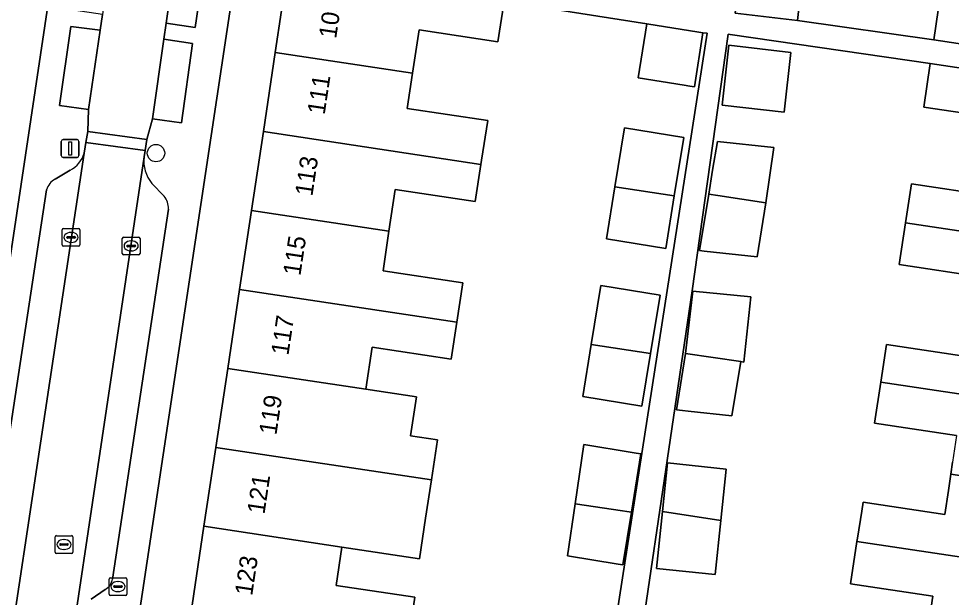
# Model space of a CAD drawing. Extents: x 163008 to 163854, y 382777 to 383982.
# Drawn here: x 163614.8 to 163667.4, y 383271.6 to 383304.2 of the extents above; entities that cross this region are included whole.
import ezdxf

# ---------------------------------------------------------------- set-up
doc = ezdxf.new("R2010")
doc.units = 0
for name, color, linetype in [('IMGEO_Boom', 7, 'Continuous'), ('IMGEO_Brandkraan', 7, 'Continuous'), ('IMGEO_Erf', 7, 'Continuous'), ('IMGEO_Kolk', 7, 'Continuous'), ('IMGEO_Lichtmast', 7, 'Continuous'), ('IMGEO_Pand', 7, 'Continuous'), ('IMGEO_Pand_nummerreeks', 7, 'Continuous'), ('IMGEO_Parkeervlak_open', 7, 'Continuous'), ('IMGEO_Rijbaan_lokaal_open', 7, 'Continuous'), ('IMGEO_Rioolput', 7, 'Continuous'), ('IMGEO_Voetpad_open', 7, 'Continuous')]:
    doc.layers.add(name, color=color, linetype=linetype)

msp = doc.modelspace()

# ---------------------------------------------------------------- linework, layer by layer
at = {"layer": 'IMGEO_Boom'}
msp.add_circle((163622.543, 383296.649), 0.489, dxfattribs=at)
at = {"layer": 'IMGEO_Brandkraan'}
for p, q in [((163619.898, 383271.768), (163619.898, 383272.62)), ((163619.973, 383272.694), (163620.825, 383272.694)), ((163620.386, 383272.474), (163620.411, 383272.474)), ((163620.899, 383272.62), (163620.899, 383271.768)), ((163620.157, 383272.188), (163620.157, 383272.2)), ((163620.595, 383272.151), (163620.197, 383272.151)), ((163620.2, 383272.237), (163620.598, 383272.237)), ((163620.409, 383271.914), (163620.384, 383271.914)), ((163620.641, 383272.2), (163620.641, 383272.188)), ((163620.825, 383271.694), (163619.973, 383271.694))]:
    msp.add_line(p, q, dxfattribs=at)
for points in [[(163619.898, 383271.768), (163619.898, 383272.62)], [(163619.973, 383272.694), (163620.825, 383272.694)], [(163620.899, 383272.62), (163620.899, 383271.768)], [(163620.825, 383271.694), (163619.973, 383271.694)]]:
    msp.add_lwpolyline(points, dxfattribs=at)
for centre, radius, start, end in [((163619.975, 383272.618), 0.0765, 91.552, 178.448), ((163619.975, 383272.618), 0.0765, 91.552, 178.448), ((163620.823, 383272.618), 0.0765, 1.552, 88.448), ((163620.823, 383272.618), 0.0765, 1.552, 88.448), ((163620.197, 383272.197), 0.0403, 85.8775, 175.7526), ((163620.194, 383272.187), 0.0366, 178.938, 274.7102), ((163620.598, 383272.194), 0.043, 264.8664, 352.4533), ((163620.602, 383272.199), 0.0386, 1.7309, 96.639), ((163619.975, 383271.77), 0.0765, 181.552, 268.448), ((163619.975, 383271.77), 0.0765, 181.552, 268.448), ((163620.823, 383271.77), 0.0765, 271.552, 358.448), ((163620.823, 383271.77), 0.0765, 271.552, 358.448)]:
    msp.add_arc(centre, radius, start, end, dxfattribs=at)
for centre, major_axis, ratio, start_param, end_param in [((163620.385, 383272.194), (-0.387, 0.002), 0.722429, 4.712389, 7.853982), ((163620.41, 383272.194), (-0.39, 0.002), 0.717154, 1.570796, 4.712389)]:
    msp.add_ellipse(centre, major_axis=major_axis, ratio=ratio, start_param=start_param, end_param=end_param, dxfattribs=at)
at = {"layer": 'IMGEO_Erf'}
for points in [[(163679.889, 383360.907), (163664.081, 383363.249), (163659.743, 383335.218), (163658.351, 383326.217), (163656.981, 383317.216), (163656.609, 383313.683), (163656.621, 383313.742), (163657.071, 383316.66), (163660.231, 383316.328), (163659.748, 383313.212), (163659.274, 383310.16), (163656.61, 383310.44), (163656.272, 383310.476), (163655.965, 383307.874), (163659.102, 383307.514), (163658.715, 383304.141), (163666.408, 383303.048), (163666.795, 383305.63), (163667.104, 383307.692), (163671.602, 383307.017)], [(163648.55, 383270.749), (163653.627, 383303.427), (163653.376, 383303.437), (163652.903, 383300.384), (163652.653, 383300.425), (163652.333, 383300.477), (163649.743, 383300.899), (163650.217, 383303.952), (163642.171, 383305.204), (163641.83, 383302.939), (163637.385, 383303.608), (163637.015, 383301.155), (163636.715, 383299.165), (163641.249, 383298.483), (163640.892, 383296.249), (163640.857, 383296.013), (163640.542, 383293.921), (163636.036, 383294.6), (163635.681, 383292.24), (163635.346, 383290.016), (163639.841, 383289.339), (163639.505, 383287.107), (163639.191, 383285.023), (163634.731, 383285.695), (163634.374, 383283.327), (163637.226, 383282.896), (163636.896, 383280.699), (163638.415, 383280.47), (163638.075, 383278.213), (163637.749, 383276.051), (163637.404, 383273.759), (163633.028, 383274.42), (163632.704, 383272.264), (163637.142, 383271.595), (163636.796, 383269.296)], [(163670.3, 383298.582), (163665.839, 383299.251), (163666.207, 383301.704), (163654.924, 383303.349), (163654.815, 383303.364), (163652.783, 383288.887), (163651.472, 383279.957), (163649.867, 383269.108), (163648.518, 383260.134), (163647.168, 383251.16), (163646.796, 383247.628), (163646.572, 383246.132), (163646.459, 383244.42)], [(163669.049, 383289.67), (163666.07, 383290.117), (163664.464, 383290.358), (163664.817, 383292.711), (163665.147, 383294.915), (163669.648, 383294.24)], [(163667.691, 383280.723), (163663.069, 383281.416), (163663.417, 383283.732), (163663.735, 383285.854), (163668.374, 383285.159)], [(163666.041, 383269.554), (163666.356, 383271.65), (163661.713, 383272.346), (163662.073, 383274.743), (163662.101, 383274.932), (163662.355, 383276.442), (163662.431, 383276.95), (163667.028, 383276.261), (163667.231, 383277.615), (163667.364, 383278.545), (163667.464, 383279.211)]]:
    msp.add_lwpolyline(points, dxfattribs=at)
for points in [[(163617.064, 383309.129), (163614.133, 383309.568), (163613.435, 383304.901), (163612.765, 383300.418), (163612.095, 383295.936), (163611.424, 383291.454), (163610.754, 383286.972), (163610.084, 383282.49), (163609.414, 383278.008), (163608.744, 383273.526), (163608.073, 383269.044), (163607.403, 383264.561), (163606.733, 383260.079), (163606.062, 383255.594), (163605.388, 383251.086), (163608.303, 383250.604)], [(163625.915, 383280.05), (163626.586, 383284.503), (163627.256, 383288.957), (163627.927, 383293.411), (163628.598, 383297.865), (163629.269, 383302.324), (163629.986, 383307.085), (163627.135, 383307.514), (163618.487, 383250), (163618.346, 383249.06), (163620.803, 383248.742), (163620.284, 383245.414), (163620.668, 383245.357), (163621.015, 383247.666), (163621.194, 383248.7), (163621.39, 383250), (163621.892, 383253.327), (163622.562, 383257.78), (163623.232, 383262.235), (163623.903, 383266.688), (163624.574, 383271.142), (163625.244, 383275.595)], [(163654.467, 383299.363), (163654.564, 383300.206), (163654.854, 383302.736), (163658.354, 383302.334), (163657.967, 383298.961)], [(163647.949, 383291.823), (163648.428, 383294.752), (163648.972, 383298.083), (163652.311, 383297.537), (163651.773, 383294.246), (163651.287, 383291.277)], [(163653.715, 383294.339), (163653.935, 383295.683), (163654.202, 383297.309), (163657.393, 383296.973), (163656.94, 383293.855), (163656.44, 383290.806), (163653.455, 383291.12), (163653.193, 383291.148)], [(163647.086, 383285.845), (163647.63, 383289.175), (163650.969, 383288.629), (163650.431, 383285.339), (163649.945, 383282.369), (163646.607, 383282.915)], [(163655.703, 383284.86), (163655.52, 383284.887), (163655.021, 383281.837), (163652.554, 383282.097), (163652.24, 383282.13), (163651.889, 383282.166), (163652.411, 383285.354), (163652.818, 383288.858), (163656.09, 383288.539)], [(163646.676, 383280.205), (163649.406, 383279.758), (163649.628, 383279.722), (163649.892, 383279.679), (163649.354, 383276.391), (163648.869, 383273.419), (163648.604, 383273.462), (163645.752, 383273.929), (163646.185, 383276.87)], [(163654.392, 383275.93), (163654.07, 383272.87), (163650.763, 383273.218), (163651.1, 383276.425), (163651.389, 383279.174), (163654.697, 383278.826)]]:
    msp.add_lwpolyline(points, close=True, dxfattribs=at)
at = {"layer": 'IMGEO_Kolk'}
for p, q in [((163617.329, 383292.397), (163618.181, 383292.397)), ((163617.254, 383291.471), (163617.254, 383292.323)), ((163617.513, 383291.891), (163617.513, 383291.903)), ((163617.951, 383291.854), (163617.553, 383291.854)), ((163617.556, 383291.94), (163617.954, 383291.94)), ((163617.742, 383292.177), (163617.767, 383292.177)), ((163617.997, 383291.903), (163617.997, 383291.891)), ((163618.255, 383292.323), (163618.255, 383291.471)), ((163620.641, 383290.988), (163620.641, 383291.84)), ((163620.716, 383291.914), (163621.568, 383291.914)), ((163621.642, 383291.84), (163621.642, 383290.988)), ((163618.181, 383291.397), (163617.329, 383291.397)), ((163617.765, 383291.617), (163617.74, 383291.617)), ((163620.9, 383291.408), (163620.9, 383291.42)), ((163621.338, 383291.371), (163620.94, 383291.371)), ((163620.943, 383291.457), (163621.341, 383291.457)), ((163621.129, 383291.694), (163621.154, 383291.694)), ((163621.384, 383291.42), (163621.384, 383291.408)), ((163621.568, 383290.914), (163620.716, 383290.914)), ((163621.152, 383291.134), (163621.127, 383291.134))]:
    msp.add_line(p, q, dxfattribs=at)
for points in [[(163617.329, 383292.397), (163618.181, 383292.397)], [(163617.254, 383291.471), (163617.254, 383292.323)], [(163618.255, 383292.323), (163618.255, 383291.471)], [(163620.641, 383290.988), (163620.641, 383291.84)], [(163620.716, 383291.914), (163621.568, 383291.914)], [(163621.642, 383291.84), (163621.642, 383290.988)], [(163618.181, 383291.397), (163617.329, 383291.397)], [(163621.568, 383290.914), (163620.716, 383290.914)]]:
    msp.add_lwpolyline(points, dxfattribs=at)
for centre, radius, start, end in [((163617.331, 383292.321), 0.0765, 91.552, 178.448), ((163617.331, 383292.321), 0.0765, 91.552, 178.448), ((163618.179, 383292.321), 0.0765, 1.552, 88.448), ((163618.179, 383292.321), 0.0765, 1.552, 88.448), ((163617.553, 383291.9), 0.0403, 85.8775, 175.7526), ((163617.55, 383291.89), 0.0366, 178.938, 274.7102), ((163617.954, 383291.897), 0.043, 264.8664, 352.4533), ((163617.958, 383291.902), 0.0386, 1.7309, 96.639), ((163620.718, 383291.838), 0.0765, 91.552, 178.448), ((163620.718, 383291.838), 0.0765, 91.552, 178.448), ((163621.566, 383291.838), 0.0765, 1.552, 88.448), ((163621.566, 383291.838), 0.0765, 1.552, 88.448), ((163617.331, 383291.473), 0.0765, 181.552, 268.448), ((163617.331, 383291.473), 0.0765, 181.552, 268.448), ((163618.179, 383291.473), 0.0765, 271.552, 358.448), ((163618.179, 383291.473), 0.0765, 271.552, 358.448), ((163620.94, 383291.417), 0.0403, 85.8775, 175.7526), ((163620.937, 383291.407), 0.0366, 178.938, 274.7102), ((163621.341, 383291.414), 0.043, 264.8664, 352.4533), ((163621.345, 383291.419), 0.0386, 1.7309, 96.639), ((163620.718, 383290.99), 0.0765, 181.552, 268.448), ((163620.718, 383290.99), 0.0765, 181.552, 268.448), ((163621.566, 383290.99), 0.0765, 271.552, 358.448), ((163621.566, 383290.99), 0.0765, 271.552, 358.448)]:
    msp.add_arc(centre, radius, start, end, dxfattribs=at)
for centre, major_axis, ratio, start_param, end_param in [((163617.741, 383291.897), (-0.387, 0.002), 0.722429, 4.712389, 7.853982), ((163617.766, 383291.897), (-0.39, 0.002), 0.717154, 1.570796, 4.712389), ((163621.128, 383291.414), (-0.387, 0.002), 0.722429, 4.712389, 7.853982), ((163621.153, 383291.414), (-0.39, 0.002), 0.717154, 1.570796, 4.712389)]:
    msp.add_ellipse(centre, major_axis=major_axis, ratio=ratio, start_param=start_param, end_param=end_param, dxfattribs=at)
at = {"layer": 'IMGEO_Lichtmast'}
for p, q in [((163617.204, 383296.513), (163617.204, 383297.313)), ((163617.204, 383297.313), (163617.204, 383296.513)), ((163617.304, 383297.413), (163618.094, 383297.413)), ((163618.094, 383297.413), (163617.304, 383297.413)), ((163618.194, 383297.313), (163618.194, 383296.513)), ((163618.194, 383296.513), (163618.194, 383297.313)), ((163618.094, 383296.413), (163617.304, 383296.413)), ((163617.304, 383296.413), (163618.094, 383296.413))]:
    msp.add_line(p, q, dxfattribs=at)
msp.add_lwpolyline([(163617.624, 383297.288), (163617.774, 383297.288), (163617.774, 383296.538), (163617.624, 383296.538), (163617.624, 383297.288)], dxfattribs=at)
for centre, start, end in [((163617.304, 383297.313), 90, 180), ((163617.304, 383297.313), 90, 180), ((163618.094, 383297.313), 0, 90), ((163618.094, 383297.313), 360, 90), ((163617.304, 383296.513), 180, 270), ((163617.304, 383296.513), 180, 270), ((163618.094, 383296.513), 270, 0), ((163618.094, 383296.513), 270, 0)]:
    msp.add_arc(centre, 0.1, start, end, dxfattribs=at)
at = {"layer": 'IMGEO_Pand'}
for points in [[(163659.102, 383307.514), (163655.965, 383307.874), (163655.602, 383307.916), (163655.215, 383304.543), (163658.715, 383304.141)], [(163679.333, 383305.856), (163671.602, 383307.017), (163667.104, 383307.692), (163666.795, 383305.63), (163666.408, 383303.048), (163670.912, 383302.373), (163673.691, 383301.96), (163678.637, 383301.225)], [(163629.269, 383302.324), (163637.015, 383301.155), (163637.385, 383303.608), (163641.83, 383302.939), (163642.171, 383305.204), (163637.727, 383305.873), (163634.926, 383306.312), (163629.986, 383307.085)], [(163653.376, 383303.437), (163653.15, 383303.474), (163650.217, 383303.952), (163649.743, 383300.899), (163652.333, 383300.477), (163652.653, 383300.425), (163652.903, 383300.384)], [(163654.564, 383300.206), (163654.467, 383299.363), (163657.967, 383298.961), (163658.354, 383302.334), (163654.854, 383302.736)], [(163636.715, 383299.165), (163637.015, 383301.155), (163629.269, 383302.324), (163628.598, 383297.865), (163640.857, 383296.013), (163640.892, 383296.249), (163641.249, 383298.483)], [(163678.43, 383299.85), (163673.488, 383300.605), (163670.71, 383301.029), (163666.207, 383301.704), (163665.839, 383299.251), (163670.3, 383298.582), (163669.992, 383296.531), (163677.757, 383295.368)], [(163640.857, 383296.013), (163628.598, 383297.865), (163627.927, 383293.411), (163635.681, 383292.24), (163636.036, 383294.6), (163640.542, 383293.921)], [(163651.773, 383294.246), (163652.311, 383297.537), (163648.972, 383298.083), (163648.428, 383294.752)], [(163653.715, 383294.339), (163654.235, 383294.261), (163656.94, 383293.855), (163657.393, 383296.973), (163654.202, 383297.309), (163653.935, 383295.683)], [(163669.992, 383296.531), (163669.648, 383294.24), (163665.147, 383294.915), (163664.817, 383292.711), (163677.082, 383290.874), (163677.757, 383295.368)], [(163651.773, 383294.246), (163648.428, 383294.752), (163647.949, 383291.823), (163651.287, 383291.277)], [(163656.94, 383293.855), (163654.235, 383294.261), (163653.715, 383294.339), (163653.193, 383291.148), (163653.455, 383291.12), (163656.44, 383290.806)], [(163635.681, 383292.24), (163627.927, 383293.411), (163627.256, 383288.957), (163639.505, 383287.107), (163639.841, 383289.339), (163635.346, 383290.016)], [(163677.082, 383290.874), (163664.817, 383292.711), (163664.464, 383290.358), (163666.07, 383290.117), (163669.049, 383289.67), (163668.823, 383287.517), (163676.407, 383286.381)], [(163627.256, 383288.957), (163626.586, 383284.503), (163634.374, 383283.327), (163634.731, 383285.695), (163639.191, 383285.023), (163639.505, 383287.107)], [(163647.086, 383285.845), (163650.431, 383285.339), (163650.969, 383288.629), (163647.63, 383289.175)], [(163656.09, 383288.539), (163652.818, 383288.858), (163652.411, 383285.354), (163655.52, 383284.887), (163655.703, 383284.86)], [(163676.407, 383286.381), (163668.823, 383287.517), (163668.708, 383287.389), (163668.374, 383285.159), (163663.735, 383285.854), (163663.417, 383283.732), (163675.732, 383281.887)], [(163647.086, 383285.845), (163646.607, 383282.915), (163649.945, 383282.369), (163650.431, 383285.339)], [(163655.52, 383284.887), (163652.411, 383285.354), (163651.889, 383282.166), (163652.24, 383282.13), (163652.554, 383282.097), (163655.021, 383281.837)], [(163634.374, 383283.327), (163626.586, 383284.503), (163625.915, 383280.05), (163638.075, 383278.213), (163638.415, 383280.47), (163636.896, 383280.699), (163637.226, 383282.896)], [(163675.732, 383281.887), (163663.417, 383283.732), (163663.069, 383281.416), (163667.691, 383280.723), (163667.464, 383279.211), (163667.364, 383278.545), (163675.057, 383277.393)], [(163633.028, 383274.42), (163637.404, 383273.759), (163637.749, 383276.051), (163638.075, 383278.213), (163625.915, 383280.05), (163625.244, 383275.595)], [(163646.185, 383276.87), (163648.853, 383276.467), (163649.09, 383276.431), (163649.354, 383276.391), (163649.892, 383279.679), (163649.628, 383279.722), (163649.406, 383279.758), (163646.676, 383280.205)], [(163651.1, 383276.425), (163654.392, 383275.93), (163654.697, 383278.826), (163651.389, 383279.174)], [(163675.057, 383277.393), (163667.364, 383278.545), (163667.231, 383277.615), (163667.028, 383276.261), (163662.431, 383276.95), (163662.355, 383276.442), (163662.101, 383274.932), (163662.073, 383274.743), (163674.382, 383272.9)], [(163649.354, 383276.391), (163649.09, 383276.431), (163648.853, 383276.467), (163646.185, 383276.87), (163645.752, 383273.929), (163648.604, 383273.462), (163648.869, 383273.419)], [(163651.1, 383276.425), (163650.763, 383273.218), (163654.07, 383272.87), (163654.392, 383275.93)], [(163633.028, 383274.42), (163625.244, 383275.595), (163624.574, 383271.142), (163636.796, 383269.296), (163637.142, 383271.595), (163632.704, 383272.264)], [(163674.382, 383272.9), (163662.073, 383274.743), (163661.713, 383272.346), (163666.356, 383271.65), (163666.041, 383269.554), (163673.707, 383268.406)]]:
    msp.add_lwpolyline(points, close=True, dxfattribs=at)
at = {"layer": 'IMGEO_Parkeervlak_open'}
for points in [[(163624.755, 383303.737), (163625.406, 383308.216), (163623.763, 383308.45), (163623.109, 383303.985)], [(163618.727, 383299.103), (163619.395, 383303.584), (163617.74, 383303.798), (163617.102, 383299.329)], [(163622.984, 383303.076), (163622.34, 383298.594), (163623.974, 383298.368), (163624.606, 383302.837)]]:
    msp.add_lwpolyline(points, close=True, dxfattribs=at)
for points in [[(163611.614, 383251.055), (163618.49, 383296.655)], [(163621.871, 383296.439), (163615.006, 383250.516)], [(163617.699, 383295.693), (163616.854, 383295.186)], [(163616.373, 383294.574), (163613.188, 383273.75)], [(163623.004, 383294.222), (163622.314, 383294.944)], [(163620.094, 383272.62), (163623.243, 383293.494)], [(163618.88, 383271.48), (163619.683, 383272.03)]]:
    msp.add_lwpolyline(points, dxfattribs=at)
for centre, radius, start, end in [((163617.028, 383297.051), 1.515, 296.2957, 344.8471), ((163623.813, 383296.201), 1.957, 173.0259, 219.9854), ((163617.332, 383294.315), 0.993, 118.7682, 164.9008), ((163622.142, 383293.536), 1.101, 357.8185, 38.5312), ((163619.234, 383272.781), 0.875, 300.8838, 349.3933)]:
    msp.add_arc(centre, radius, start, end, dxfattribs=at)
at = {"layer": 'IMGEO_Rijbaan_lokaal_open'}
for points in [[(163623.763, 383308.45), (163623.98, 383309.644), (163624.616, 383314.127), (163624.75, 383315.017), (163625.462, 383319.502), (163625.602, 383320.993), (163622.153, 383321.469), (163621.806, 383320.011), (163621.152, 383315.54), (163620.987, 383314.543), (163620.326, 383310.068), (163620.158, 383308.956), (163619.533, 383304.478), (163619.395, 383303.584), (163618.727, 383299.103), (163618.697, 383297.877), (163622.019, 383297.425), (163622.34, 383298.594), (163622.984, 383303.076), (163623.109, 383303.985)], [(163621.924, 383296.792), (163622.019, 383297.425), (163618.697, 383297.877), (163618.586, 383297.246)], [(163614.953, 383250.174), (163615.006, 383250.516), (163621.871, 383296.439), (163621.924, 383296.792), (163618.586, 383297.246), (163618.543, 383297.004), (163618.49, 383296.655), (163611.614, 383251.055), (163611.551, 383250.689)]]:
    msp.add_lwpolyline(points, close=True, dxfattribs=at)
at = {"layer": 'IMGEO_Rioolput'}
for p, q in [((163616.927, 383275.067), (163617.779, 383275.067)), ((163616.852, 383274.141), (163616.852, 383274.993)), ((163617.111, 383274.561), (163617.111, 383274.573)), ((163617.549, 383274.524), (163617.151, 383274.524)), ((163617.154, 383274.61), (163617.552, 383274.61)), ((163617.34, 383274.847), (163617.365, 383274.847)), ((163617.595, 383274.573), (163617.595, 383274.561)), ((163617.853, 383274.993), (163617.853, 383274.141)), ((163617.779, 383274.067), (163616.927, 383274.067)), ((163617.363, 383274.287), (163617.338, 383274.287))]:
    msp.add_line(p, q, dxfattribs=at)
for points in [[(163616.927, 383275.067), (163617.779, 383275.067)], [(163616.852, 383274.141), (163616.852, 383274.993)], [(163617.853, 383274.993), (163617.853, 383274.141)], [(163617.779, 383274.067), (163616.927, 383274.067)]]:
    msp.add_lwpolyline(points, dxfattribs=at)
for centre, radius, start, end in [((163616.929, 383274.991), 0.0765, 91.552, 178.448), ((163616.929, 383274.991), 0.0765, 91.552, 178.448), ((163617.777, 383274.991), 0.0765, 1.552, 88.448), ((163617.777, 383274.991), 0.0765, 1.552, 88.448), ((163617.151, 383274.57), 0.0403, 85.8775, 175.7526), ((163617.148, 383274.56), 0.0366, 178.938, 274.7102), ((163617.552, 383274.567), 0.043, 264.8664, 352.4533), ((163617.556, 383274.572), 0.0386, 1.7309, 96.639), ((163616.929, 383274.143), 0.0765, 181.552, 268.448), ((163616.929, 383274.143), 0.0765, 181.552, 268.448), ((163617.777, 383274.143), 0.0765, 271.552, 358.448), ((163617.777, 383274.143), 0.0765, 271.552, 358.448)]:
    msp.add_arc(centre, radius, start, end, dxfattribs=at)
for centre, major_axis, ratio, start_param, end_param in [((163617.339, 383274.567), (-0.387, 0.002), 0.722429, 4.712389, 7.853982), ((163617.364, 383274.567), (-0.39, 0.002), 0.717154, 1.570796, 4.712389)]:
    msp.add_ellipse(centre, major_axis=major_axis, ratio=ratio, start_param=start_param, end_param=end_param, dxfattribs=at)
at = {"layer": 'IMGEO_Voetpad_open'}
for points in [[(163629.103, 383367.415), (163629.166, 383367.856), (163629.256, 383368.49), (163626.017, 383368.942), (163617.252, 383310.387), (163617.064, 383309.129), (163608.303, 383250.604), (163611.443, 383250.058), (163611.551, 383250.689), (163611.614, 383251.055)], [(163670.912, 383302.373), (163666.408, 383303.048), (163658.715, 383304.141), (163655.215, 383304.543), (163655.602, 383307.916), (163655.965, 383307.874), (163656.272, 383310.476), (163656.089, 383310.495), (163656.609, 383313.683), (163656.981, 383317.216), (163658.351, 383326.217), (163659.743, 383335.218), (163664.081, 383363.249), (163679.889, 383360.907)], [(163618.697, 383297.877), (163618.727, 383299.103), (163617.102, 383299.329), (163617.74, 383303.798), (163619.395, 383303.584), (163619.533, 383304.478), (163617.885, 383304.72), (163618.543, 383309.192), (163620.158, 383308.956), (163620.326, 383310.068), (163618.712, 383310.303), (163619.348, 383314.786), (163620.987, 383314.543), (163621.152, 383315.54), (163619.498, 383315.767), (163620.186, 383320.23), (163621.806, 383320.011), (163622.153, 383321.469), (163622.266, 383322.099), (163622.309, 383322.342)], [(163625.711, 383321.848), (163625.683, 383321.628), (163625.602, 383320.993), (163625.462, 383319.502), (163627.046, 383319.27), (163626.406, 383314.773), (163624.75, 383315.017), (163624.616, 383314.127), (163626.255, 383313.884), (163625.594, 383309.409), (163623.98, 383309.644), (163623.763, 383308.45), (163625.406, 383308.216), (163624.755, 383303.737), (163623.109, 383303.985), (163622.984, 383303.076), (163624.606, 383302.837), (163623.974, 383298.368), (163622.34, 383298.594), (163622.019, 383297.425), (163621.924, 383296.792), (163621.871, 383296.439)], [(163615.006, 383250.516), (163614.953, 383250.174), (163614.926, 383250), (163614.854, 383249.541), (163618.346, 383249.06), (163618.487, 383250), (163627.135, 383307.514)], [(163642.171, 383305.204), (163650.217, 383303.952), (163653.15, 383303.474), (163653.376, 383303.437), (163653.627, 383303.427), (163648.55, 383270.749), (163648.04, 383267.457), (163647.531, 383264.172), (163647.244, 383262.318), (163646.661, 383258.555), (163646.198, 383255.416), (163646.002, 383254.084), (163645.787, 383252.624), (163645.347, 383249.643), (163644.859, 383246.335), (163644.672, 383245.046), (163628.784, 383247.565), (163626.139, 383247.957), (163621.194, 383248.7), (163621.015, 383247.666), (163625.99, 383246.918), (163629.577, 383246.379), (163629.397, 383245.183)], [(163669.638, 383241.316), (163664.694, 383242.058), (163662.245, 383242.425), (163649.766, 383244.072), (163646.459, 383244.42), (163646.572, 383246.132), (163646.796, 383247.628), (163647.168, 383251.16), (163648.518, 383260.134), (163649.867, 383269.108), (163651.472, 383279.957), (163652.783, 383288.887), (163654.815, 383303.364), (163654.924, 383303.349), (163666.207, 383301.704), (163670.71, 383301.029)], [(163618.49, 383296.655), (163618.543, 383297.004), (163618.586, 383297.246), (163618.697, 383297.877)], [(163616.854, 383295.186), (163617.699, 383295.693)], [(163613.188, 383273.75), (163616.373, 383294.574)], [(163622.314, 383294.944), (163623.004, 383294.222)], [(163623.243, 383293.494), (163620.094, 383272.62)], [(163619.683, 383272.03), (163618.88, 383271.48)]]:
    msp.add_lwpolyline(points, dxfattribs=at)
for centre, radius, start, end in [((163617.028, 383297.051), 1.515, 296.2957, 344.8471), ((163623.813, 383296.201), 1.957, 173.0259, 219.9854), ((163617.332, 383294.315), 0.993, 118.7682, 164.9008), ((163622.142, 383293.536), 1.101, 357.8185, 38.5312), ((163619.234, 383272.781), 0.875, 300.8838, 349.3933)]:
    msp.add_arc(centre, radius, start, end, dxfattribs=at)

# ---------------------------------------------------------------- texts
at = {"layer": 'IMGEO_Pand_nummerreeks'}
for s, rotation, p in [('109', 81.4364, (163632.7, 383303.079)), ('111', 81.4345, (163632.054, 383298.789)), ('113', 81.4364, (163631.361, 383294.187)), ('115', 81.4364, (163630.685, 383289.696)), ('117', 81.4364, (163630.008, 383285.205)), ('119', 81.4345, (163629.332, 383280.714)), ('121', 81.4364, (163628.659, 383276.244)), ('123', 81.4364, (163627.965, 383271.641))]:
    msp.add_text(s, height=1, rotation=rotation, dxfattribs=at).set_placement(p)

doc.saveas('drawing.dxf')
